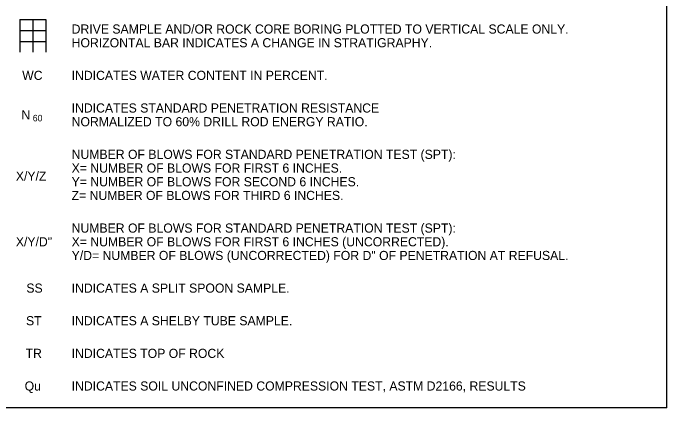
# Model space of a CAD drawing. Extents: x 0 to 34, y 0 to 22.
# Drawn here: x 11.81 to 21.83, y 9.68 to 15.73 of the extents above; entities that cross this region are included whole.
import ezdxf

# ---------------------------------------------------------------- set-up
doc = ezdxf.new("R2010")
doc.units = 0
for name, color, linetype in [('GT_Project_Soil_Boring', 7, 'Continuous'), ('SH_Data', 7, 'Continuous'), ('SH_Text', 7, 'Continuous')]:
    doc.layers.add(name, color=color, linetype=linetype)

msp = doc.modelspace()

# ---------------------------------------------------------------- linework, layer by layer
at = {"layer": 'GT_Project_Soil_Boring'}
for p, q in [((11.917, 15.627), (12.317, 15.627)), ((11.917, 15.627), (11.917, 15.127)), ((12.117, 15.627), (12.117, 15.127)), ((12.317, 15.627), (12.317, 15.127)), ((11.917, 15.46), (12.317, 15.46)), ((11.917, 15.293), (12.317, 15.293))]:
    msp.add_line(p, q, dxfattribs=at)
at = {"layer": 'SH_Data'}
for q in [(21.833, 21), (11.667, 9.676)]:
    msp.add_line((21.833, 9.676), q, dxfattribs=at)

# ---------------------------------------------------------------- texts
for s, height, p in [('WC', 0.14, (11.954, 14.702)), ('N', 0.14, (11.942, 14.097)), ('60', 0.1, (12.116, 14.067)), ('X/Y/Z', 0.14, (11.857, 13.158)), ('X/Y/D"', 0.14, (11.857, 12.152)), ('SS', 0.14, (12.018, 11.442)), ('ST ', 0.14, (12.013, 10.942)), ('TR', 0.14, (12.006, 10.442)), ('Qu', 0.14, (11.992, 9.942))]:
    msp.add_text(s, height=height, dxfattribs=at).set_placement(p)
at = {"layer": 'SH_Text'}
for s, p in [('DRIVE SAMPLE AND/OR ROCK CORE BORING PLOTTED TO VERTICAL SCALE ONLY.', (12.712, 15.412)), ('HORIZONTAL BAR INDICATES A CHANGE IN STRATIGRAPHY.', (12.712, 15.202)), ('INDICATES WATER CONTENT IN PERCENT.', (12.712, 14.702)), ('INDICATES STANDARD PENETRATION RESISTANCE', (12.712, 14.202)), ('NORMALIZED TO 60% DRILL ROD ENERGY RATIO.', (12.712, 13.992)), ('NUMBER OF BLOWS FOR STANDARD PENETRATION TEST (SPT):', (12.712, 13.492)), ('X= NUMBER OF BLOWS FOR FIRST 6 INCHES.', (12.712, 13.282)), ('Y= NUMBER OF BLOWS FOR SECOND 6 INCHES.', (12.712, 13.072)), ('Z= NUMBER OF BLOWS FOR THIRD 6 INCHES.', (12.712, 12.862)), ('NUMBER OF BLOWS FOR STANDARD PENETRATION TEST (SPT):', (12.712, 12.362)), ('X= NUMBER OF BLOWS FOR FIRST 6 INCHES (UNCORRECTED).', (12.712, 12.152)), ('Y/D= NUMBER OF BLOWS (UNCORRECTED) FOR D" OF PENETRATION AT REFUSAL.', (12.712, 11.942)), ('INDICATES A SPLIT SPOON SAMPLE.', (12.712, 11.442)), ('INDICATES A SHELBY TUBE SAMPLE.', (12.712, 10.942)), ('INDICATES TOP OF ROCK', (12.712, 10.442)), ('INDICATES SOIL UNCONFINED COMPRESSION TEST, ASTM D2166, RESULTS', (12.712, 9.942))]:
    msp.add_text(s, height=0.14, dxfattribs=at).set_placement(p)

doc.saveas('drawing.dxf')
